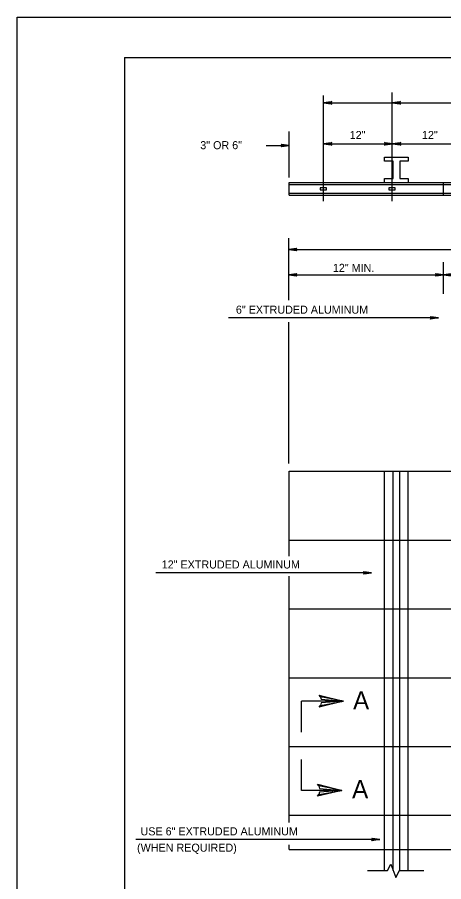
# Model space of a CAD drawing. Extents: x 647822 to 649292, y 298458 to 299646.
# Drawn here: x 647822.3 to 647981.4, y 299323.4 to 299645.6 of the extents above; entities that cross this region are included whole.
import ezdxf

# ---------------------------------------------------------------- set-up
doc = ezdxf.new("R2010")
doc.units = 0
for name, color, linetype in [('1', 7, 'Continuous'), ('2', 7, 'Continuous'), ('3', 7, 'Continuous'), ('XCS-GRID-MIN', 7, 'Continuous')]:
    doc.layers.add(name, color=color, linetype=linetype)

# ---------------------------------------------------------------- blocks, each defined once
blk = doc.blocks.new('RARROW')
at = {"layer": '3'}
blk.add_lwpolyline([(-2.2695, 0.285), (-2.184875, 0.12075), (0, 0), (-2.2695, 0.285), (-2.38575, 0.384625), (0, 0), (-2.183125, -0.108), (-2.262875, -0.2705), (0, 0), (-2.38575, -0.379125), (-2.262875, -0.2705)], dxfattribs=at)

msp = doc.modelspace()

# ---------------------------------------------------------------- linework, layer by layer
at = {"layer": '1'}
for q in [(648648.31, 299630.63), (647862.31, 299066.63)]:
    msp.add_line((647862.31, 299630.63), q, dxfattribs=at)
at = {"layer": '2'}
for p, q in [((647936.63, 299577.1), (647936.63, 299616.48)), ((647962.25, 299577.1), (647962.25, 299617.6)), ((647936.63, 299613.73), (647962.25, 299613.73)), ((647936.63, 299613.73), (647936.63, 299613.73)), ((647962.25, 299613.73), (647987.88, 299613.73)), ((647962.25, 299613.73), (647962.25, 299613.73)), ((647923.75, 299585.85), (647923.75, 299603.1)), ((647915.15, 299597.85), (647923.75, 299597.85)), ((647936.63, 299598.48), (647962.38, 299598.48)), ((647962.38, 299598.48), (647987.88, 299598.48)), ((647959.38, 299591.98), (647959.38, 299593.48)), ((647959.38, 299593.48), (647968.13, 299593.48)), ((647968.13, 299593.48), (647968.13, 299591.98)), ((647962.63, 299591.98), (647959.38, 299591.98)), ((647962.63, 299585.48), (647962.63, 299591.98)), ((647968.13, 299591.98), (647965, 299591.98)), ((647965, 299591.98), (647965, 299585.48)), ((647923.75, 299584.1), (648129, 299584.1)), ((647923.75, 299579.35), (647923.75, 299584.1)), ((647959.38, 299583.98), (647959.38, 299585.48)), ((647959.38, 299585.48), (647962.63, 299585.48)), ((647965, 299585.48), (647968.13, 299585.48)), ((647968.13, 299585.48), (647968.13, 299583.98)), ((647981.38, 299579.35), (647981.38, 299584.1)), ((647923.75, 299583.35), (648129, 299583.35)), ((647937.75, 299582.1), (647935.38, 299582.1)), ((647935.38, 299582.1), (647935.38, 299581.35)), ((647935.38, 299581.35), (647937.75, 299581.35)), ((647937.75, 299581.35), (647937.75, 299582.1)), ((647963.38, 299582.1), (647961, 299582.1)), ((647961, 299582.1), (647961, 299581.35)), ((647961, 299581.35), (647963.38, 299581.35)), ((647963.38, 299581.35), (647963.38, 299582.1)), ((647923.75, 299580.1), (648129, 299580.1)), ((647923.75, 299579.35), (648129, 299579.35)), ((647923.63, 299540.24), (647923.63, 299563.35)), ((647923.63, 299559.1), (648128.88, 299559.1)), ((647981.38, 299542.6), (647981.38, 299554.35)), ((647923.63, 299549.6), (647981.38, 299549.6)), ((647981.38, 299549.6), (648128.88, 299549.6)), ((647979.5, 299533.65), (647901.11, 299533.65)), ((647923.63, 299479.35), (647923.63, 299532.01)), ((647923.75, 299476.48), (648129, 299476.48)), ((647923.75, 299444.73), (647923.75, 299476.48)), ((647959.38, 299327.62), (647959.38, 299476.48)), ((647962.63, 299327.62), (647962.63, 299476.48)), ((647965, 299327.62), (647965, 299476.48)), ((647968.13, 299327.62), (647968.13, 299476.48)), ((647923.75, 299450.73), (648129, 299450.73)), ((647954.5, 299438.6), (647873.98, 299438.6)), ((647923.75, 299345.54), (647923.75, 299437.35)), ((647923.75, 299425.1), (648129, 299425.1)), ((647923.75, 299399.48), (648129, 299399.48)), ((647944, 299390.71), (647928.41, 299390.71)), ((647928.41, 299379.23), (647928.41, 299390.71)), ((647923.75, 299373.85), (648129, 299373.85)), ((647928.41, 299357.49), (647928.41, 299368.97)), ((647943.38, 299357.49), (647928.41, 299357.49)), ((647923.75, 299348.23), (648129, 299348.23)), ((647957.63, 299339.21), (647866.51, 299339.21)), ((647923.75, 299335.48), (647923.75, 299337.23)), ((647923.75, 299335.48), (648129, 299335.48)), ((647960.5, 299327.62), (647961.75, 299330)), ((647961.75, 299330), (647963.56, 299325.01)), ((647953, 299327.62), (647960.5, 299327.62)), ((647963.56, 299325.01), (647964.94, 299327.62)), ((647964.94, 299327.62), (647974, 299327.62))]:
    msp.add_line(p, q, dxfattribs=at)
at = {"layer": 'XCS-GRID-MIN'}
msp.add_lwpolyline([(647822.31, 299645.63), (648663.31, 299645.63), (648663.31, 299051.63), (647822.31, 299051.63)], close=True, dxfattribs=at)

# ---------------------------------------------------------------- block references
at = {"layer": '2', "xscale": 1.2574347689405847, "yscale": 1.3092961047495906, "rotation": 180}
for p in [(647936.63, 299613.73), (647962.25, 299613.73), (647936.63, 299598.48), (647962.38, 299598.48), (647923.63, 299559.1), (647923.63, 299549.6), (647981.38, 299549.6)]:
    msp.add_blockref('RARROW', p, dxfattribs=at)
at = {"layer": '2'}
for p, xscale, yscale in [((647923.75, 299597.85), 1.2574347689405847, 1.3092961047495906), ((647962.38, 299598.48), 1.2574347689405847, 1.3092961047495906), ((647981.38, 299549.6), 1.2574347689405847, 1.3092961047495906), ((647979.5, 299533.65), 1.2574347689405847, 1.3092961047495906), ((647954.5, 299438.6), 1.2574347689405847, 1.3092961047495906), ((647944, 299390.71), 3.772304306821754, 5.891832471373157), ((647943.38, 299357.49), 3.772304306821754, 5.891832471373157), ((647957.63, 299339.21), 1.2574347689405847, 1.3092961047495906)]:
    msp.add_blockref('RARROW', p, dxfattribs=dict(at, xscale=xscale, yscale=yscale))

# ---------------------------------------------------------------- texts
for s, height, p in [('12"', 3, (647946.35, 299600.26)), ('12"', 3, (647973.31, 299600.26)), ('3" OR 6"', 3, (647890.6, 299596.46)), ('12" MIN.', 3, (647940.08, 299550.73)), ('6" EXTRUDED ALUMINUM', 3, (647903.89, 299535.15)), ('12" EXTRUDED ALUMINUM', 3, (647876.21, 299440.18)), ('A', 6.75, (647947.61, 299387.65)), ('A', 6.75, (647947.24, 299354.56)), ('USE 6" EXTRUDED ALUMINUM', 3, (647868.31, 299340.71)), ('(WHEN REQUIRED)', 3, (647867.01, 299334.62))]:
    msp.add_text(s, height=height, dxfattribs=at).set_placement(p)

doc.saveas('drawing.dxf')
